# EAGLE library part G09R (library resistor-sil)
SIL RESISTOR
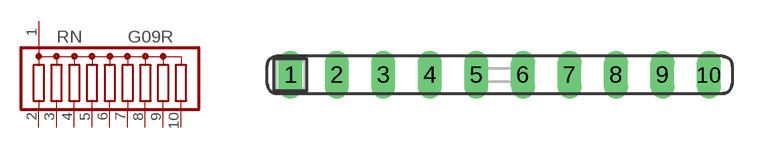
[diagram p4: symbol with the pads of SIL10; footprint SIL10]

Designator prefix RN

## G09R (OC_FARNELL: unknown; OC_NEWARK: unknown)  [SIL10]
1  1  pas
2  2  pas
3  3  pas
4  4  pas
5  5  pas
6  6  pas
7  7  pas
8  8  pas
9  9  pas
10  10  pas

## Footprint SIL10 (pad centres in mm)
Single In Line
drill 0.813 long: 1 -11.43,0; 2 -8.89,0; 3 -6.35,0; 4 -3.81,0; 5 -1.27,0; 6 1.27,0; 7 3.81,0; 8 6.35,0; 9 8.89,0; 10 11.43,0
